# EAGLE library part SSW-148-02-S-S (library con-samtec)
THROUGH-HOLE .025" SQ POST SOCKET Source: Samtec SSW.pdf
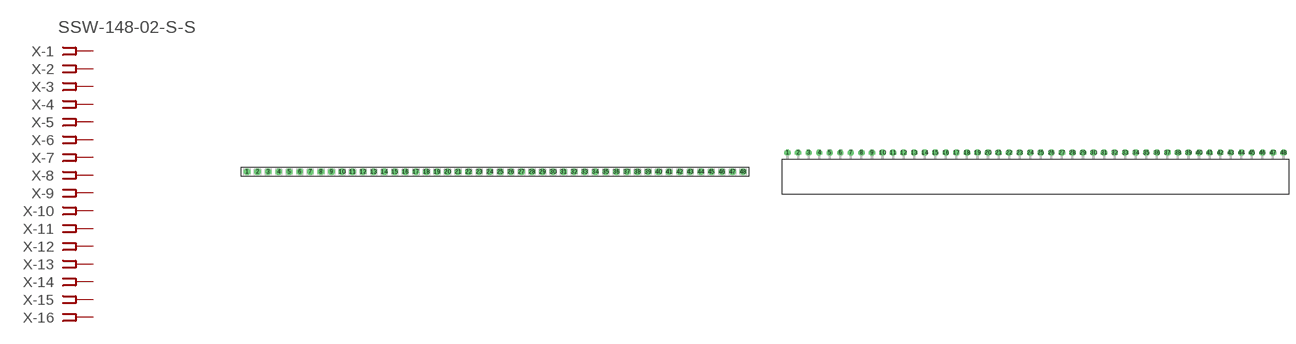
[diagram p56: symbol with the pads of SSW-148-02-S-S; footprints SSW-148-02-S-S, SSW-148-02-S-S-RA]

Designator prefix X; gates -1=FPINV -2=FPIN -3=FPIN -4=FPIN -5=FPIN -6=FPIN -7=FPIN -8=FPIN -9=FPIN -10=FPIN -11=FPIN -12=FPIN -13=FPIN -14=FPIN -15=FPIN -16=FPIN -17=FPIN -18=FPIN -19=FPIN -20=FPIN -21=FPIN -22=FPIN -23=FPIN -24=FPIN -25=FPIN -26=FPIN -27=FPIN -28=FPIN -29=FPIN -30=FPIN -31=FPIN -32=FPIN -33=FPIN -34=FPIN -35=FPIN -36=FPIN -37=FPIN -38=FPIN -39=FPIN -40=FPIN -41=FPIN -42=FPIN -43=FPIN -44=FPIN -45=FPIN -46=FPIN -47=FPIN -48=FPIN

## SSW-148-02-S-S (OC_FARNELL: unknown; OC_NEWARK: unknown)  [SSW-148-02-S-S]
1  -1:1  pas
2  -2:1  pas
3  -3:1  pas
4  -4:1  pas
5  -5:1  pas
6  -6:1  pas
7  -7:1  pas
8  -8:1  pas
9  -9:1  pas
10  -10:1  pas
11  -11:1  pas
12  -12:1  pas
13  -13:1  pas
14  -14:1  pas
15  -15:1  pas
16  -16:1  pas
17  -17:1  pas
18  -18:1  pas
19  -19:1  pas
20  -20:1  pas
21  -21:1  pas
22  -22:1  pas
23  -23:1  pas
24  -24:1  pas
25  -25:1  pas
26  -26:1  pas
27  -27:1  pas
28  -28:1  pas
29  -29:1  pas
30  -30:1  pas
31  -31:1  pas
32  -32:1  pas
33  -33:1  pas
34  -34:1  pas
35  -35:1  pas
36  -36:1  pas
37  -37:1  pas
38  -38:1  pas
39  -39:1  pas
40  -40:1  pas
41  -41:1  pas
42  -42:1  pas
43  -43:1  pas
44  -44:1  pas
45  -45:1  pas
46  -46:1  pas
47  -47:1  pas
48  -48:1  pas

## SSW-148-02-S-S-RA (OC_FARNELL: unknown; OC_NEWARK: unknown)  [SSW-148-02-S-S-RA]
Pads as for SSW-148-02-S-S

## Footprint SSW-148-02-S-S (pad centres in mm)
THROUGH-HOLE .025" SQ POST SOCKET Source: Samtec SSW.pdf
drill 1 pad 1.5 octagon: 1 -59.69,0; 2 -57.15,0; 3 -54.61,0; 4 -52.07,0; 5 -49.53,0; 6 -46.99,0; 7 -44.45,0; 8 -41.91,0; 9 -39.37,0; 10 -36.83,0; 11 -34.29,0; 12 -31.75,0; 13 -29.21,0; 14 -26.67,0; 15 -24.13,0; 16 -21.59,0; 17 -19.05,0; 18 -16.51,0; 19 -13.97,0; 20 -11.43,0; 21 -8.89,0; 22 -6.35,0; 23 -3.81,0; 24 -1.27,0; 25 1.27,0; 26 3.81,0; 27 6.35,0; 28 8.89,0; 29 11.43,0; 30 13.97,0; 31 16.51,0; 32 19.05,0; 33 21.59,0; 34 24.13,0; 35 26.67,0; 36 29.21,0; 37 31.75,0; 38 34.29,0; 39 36.83,0; 40 39.37,0; 41 41.91,0; 42 44.45,0; 43 46.99,0; 44 49.53,0; 45 52.07,0; 46 54.61,0; 47 57.15,0; 48 59.69,0

## Footprint SSW-148-02-S-S-RA (pad centres in mm)
THROUGH-HOLE .025" SQ POST SOCKET Source: Samtec SSW.pdf
drill 1 pad 1.5 octagon: 1 -59.69,1.524; 2 -57.15,1.524; 3 -54.61,1.524; 4 -52.07,1.524; 5 -49.53,1.524; 6 -46.99,1.524; 7 -44.45,1.524; 8 -41.91,1.524; 9 -39.37,1.524; 10 -36.83,1.524; 11 -34.29,1.524; 12 -31.75,1.524; 13 -29.21,1.524; 14 -26.67,1.524; 15 -24.13,1.524; 16 -21.59,1.524; 17 -19.05,1.524; 18 -16.51,1.524; 19 -13.97,1.524; 20 -11.43,1.524; 21 -8.89,1.524; 22 -6.35,1.524; 23 -3.81,1.524; 24 -1.27,1.524; 25 1.27,1.524; 26 3.81,1.524; 27 6.35,1.524; 28 8.89,1.524; 29 11.43,1.524; 30 13.97,1.524; 31 16.51,1.524; 32 19.05,1.524; 33 21.59,1.524; 34 24.13,1.524; 35 26.67,1.524; 36 29.21,1.524; 37 31.75,1.524; 38 34.29,1.524; 39 36.83,1.524; 40 39.37,1.524; 41 41.91,1.524; 42 44.45,1.524; 43 46.99,1.524; 44 49.53,1.524; 45 52.07,1.524; 46 54.61,1.524; 47 57.15,1.524; 48 59.69,1.524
